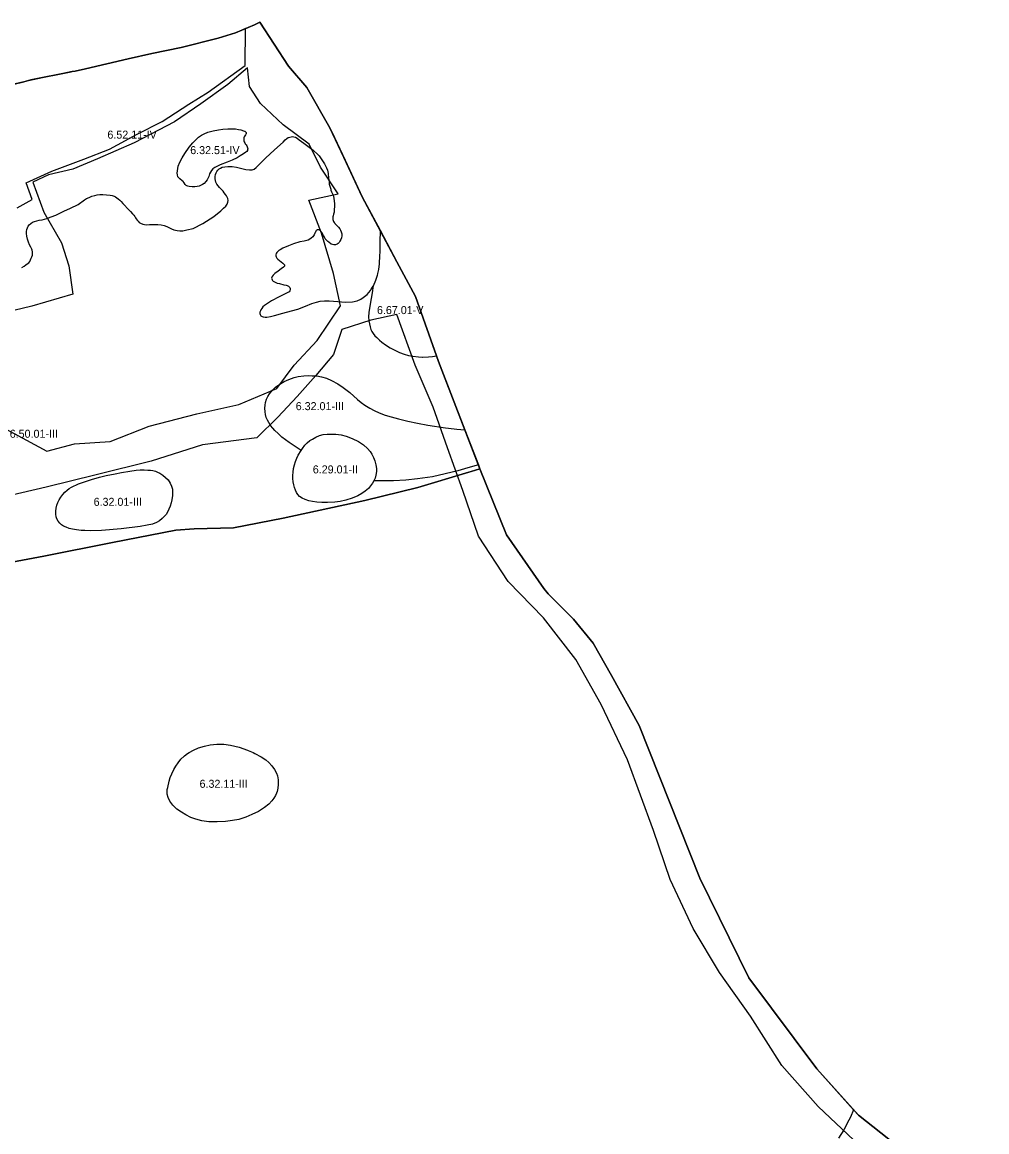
# Model space of a CAD drawing. Extents: x -555156 to -540209, y -1046851 to -1035695.
# Drawn here: x -541747 to -540542, y -1038196 to -1036810 of the extents above; entities that cross this region are included whole.
import ezdxf

# ---------------------------------------------------------------- set-up
doc = ezdxf.new("R2010")
doc.units = 0
for name, color, linetype in [('Vrstva 27', 7, 'Continuous'), ('Vrstva 28', 7, 'Continuous'), ('Vrstva 29', 7, 'Continuous')]:
    doc.layers.add(name, color=color, linetype=linetype)

msp = doc.modelspace()

# ---------------------------------------------------------------- linework, layer by layer
at = {"layer": 'Vrstva 28'}
for points in [[(-541903.43, -1036929.77), (-541877.68, -1036923.71), (-541848.08, -1036913.72), (-541790.28, -1036895.14), (-541767.6, -1036889.55), (-541745.19, -1036884.02), (-541736.43, -1036881.86), (-541685.69, -1036871.7), (-541684.42, -1036871.45), (-541680.65, -1036870.7), (-541667.8, -1036868.13), (-541614.57, -1036855.58), (-541584.97, -1036848.6), (-541548.46, -1036841.46), (-541501.97, -1036829.63), (-541480.4, -1036822.91), (-541472.49, -1036819.6), (-541456.86, -1036813.05), (-541450.16, -1036809.67), (-541414.05, -1036864.8), (-541391.34, -1036891.2), (-541362.63, -1036941.56)], [(-540646.21, -1038219.67), (-540701.89, -1038175.62), (-540754.02, -1038117.46), (-540838.81, -1038003.99), (-540900.32, -1037879.43), (-540976, -1037688.59), (-541010.46, -1037625.98), (-541033.4, -1037585.85), (-541058.08, -1037555.54), (-541089.68, -1037524), (-541094.93, -1037517.52), (-541141.64, -1037450.42), (-541174.98, -1037367.89), (-541226.69, -1037233.48), (-541255.41, -1037152.42), (-541278.92, -1037108.98), (-541321.98, -1037027.74), (-541345.15, -1036978.62), (-541362.63, -1036941.56), (-541391.34, -1036891.2), (-541414.05, -1036864.8), (-541450.16, -1036809.67), (-541456.86, -1036813.05), (-541472.69, -1036819.74), (-541480.4, -1036822.91), (-541501.97, -1036829.63), (-541548.46, -1036841.46), (-541584.97, -1036848.6), (-541667.8, -1036868.13), (-541680.65, -1036870.7), (-541684.42, -1036871.45), (-541745.19, -1036884.02), (-541767.6, -1036889.55)], [(-541538.19, -1036965.9), (-541533.93, -1036960.53), (-541530.23, -1036956.65), (-541526.67, -1036953.41), (-541523.11, -1036950.82), (-541519.78, -1036949.1), (-541514.85, -1036947.12), (-541508.37, -1036945.36), (-541501.67, -1036944.11), (-541496.3, -1036943.28), (-541490.2, -1036942.91), (-541484.74, -1036942.91), (-541480.67, -1036943.1), (-541476.92, -1036943.56), (-541473.73, -1036944.21), (-541470.4, -1036945.36), (-541469.42, -1036945.76), (-541469.01, -1036945.9), (-541468.55, -1036946.13), (-541468.22, -1036946.37), (-541467.98, -1036946.59), (-541467.75, -1036946.89), (-541467.5, -1036947.27), (-541467.33, -1036947.7), (-541467.24, -1036948.17), (-541467.24, -1036948.68), (-541467.33, -1036949.11), (-541467.45, -1036949.44), (-541468.05, -1036950.39), (-541468.89, -1036951.6), (-541469.55, -1036952.82), (-541469.9, -1036954.06), (-541470, -1036955.44), (-541470.05, -1036956.89), (-541469.86, -1036958.13), (-541469.47, -1036959.32), (-541468.94, -1036960.46), (-541468.25, -1036961.63), (-541467.2, -1036962.87), (-541466.24, -1036964.03), (-541465.71, -1036965.3), (-541465.37, -1036966.68), (-541465.24, -1036967.87), (-541465.34, -1036969.03), (-541465.63, -1036970.09), (-541466.27, -1036971.12), (-541467.43, -1036972.23), (-541470.54, -1036974.2), (-541474.43, -1036976.75), (-541478.55, -1036979.2), (-541484.84, -1036982.16), (-541490.84, -1036984.75), (-541499.72, -1036988.03), (-541503.75, -1036990.16), (-541506.43, -1036991.41), (-541508.88, -1036993.03), (-541510.32, -1036994.79), (-541511.75, -1036996.97), (-541512.77, -1036999.37), (-541513.83, -1037002.33), (-541515.82, -1037006.82), (-541517.66, -1037008.91), (-541519.65, -1037011.04), (-541521.83, -1037012.57), (-541525.93, -1037014.41), (-541528.24, -1037015.06), (-541531.31, -1037015.44)], [(-541362.63, -1036941.56), (-541356.79, -1036953.93), (-541343.48, -1036982.15), (-541321.98, -1037027.74), (-541299.74, -1037069.7)], [(-541493.78, -1036990.23), (-541489.97, -1036989.91), (-541484.82, -1036990.04), (-541479.25, -1036991), (-541472.4, -1036992.43), (-541467.39, -1036993.71), (-541462.94, -1036994.1), (-541459.51, -1036994.02), (-541457.29, -1036993.15), (-541454.82, -1036991.34), (-541442.99, -1036979.64), (-541431.57, -1036969.05), (-541420.76, -1036959.44), (-541418.31, -1036956.67), (-541416.13, -1036954.85), (-541414.58, -1036953.94), (-541412.76, -1036953.21), (-541411.03, -1036952.76), (-541409.35, -1036952.62), (-541407.49, -1036952.85), (-541405.62, -1036953.44), (-541403.58, -1036954.67), (-541400.74, -1036956.54), (-541394.93, -1036961), (-541389.99, -1036964.74), (-541383.39, -1036969.44), (-541377.18, -1036975.25), (-541376.11, -1036976.63), (-541373.21, -1036980.35), (-541369.31, -1036986.79), (-541366.68, -1036991.57)], [(-541531.31, -1037015.44), (-541534.48, -1037015.49), (-541538.31, -1037015.09), (-541540, -1037014.7), (-541541.11, -1037014.22), (-541542.18, -1037013.61), (-541543.38, -1037012.36), (-541544.68, -1037010.37), (-541546.02, -1037008.71), (-541547.07, -1037007.75), (-541550.15, -1037005.56), (-541552.33, -1037002.73), (-541553.06, -1037000.3), (-541553.3, -1036998.36), (-541553.06, -1036995.52), (-541552.09, -1036989.56), (-541549.96, -1036984.7), (-541547.05, -1036979.34), (-541543.69, -1036973.59), (-541538.19, -1036965.9)], [(-541734.88, -1037093.42), (-541736.09, -1037090.84), (-541737.76, -1037087.81), (-541739.11, -1037084.71), (-541740.46, -1037080.97), (-541741.34, -1037077.14), (-541741.74, -1037073.8), (-541741.74, -1037071.17), (-541741.34, -1037068.63), (-541740.62, -1037066.48), (-541739.59, -1037064.49), (-541738.24, -1037062.82), (-541736.17, -1037061.06), (-541734.02, -1037059.71), (-541731.55, -1037058.6), (-541728.85, -1037057.8), (-541725.9, -1037057.24), (-541722.24, -1037056.61), (-541716.28, -1037054.78), (-541710.95, -1037053.02), (-541704.94, -1037050.64), (-541695.07, -1037045.94), (-541686.64, -1037042.12), (-541677.17, -1037037.5), (-541669.24, -1037031.86), (-541666.61, -1037030.13), (-541663.42, -1037028.54), (-541659.88, -1037027.17), (-541656.15, -1037026.08), (-541653.28, -1037025.4), (-541650.01, -1037024.99), (-541646.46, -1037024.9), (-541641.6, -1037025.26), (-541637.24, -1037025.67), (-541634.42, -1037026.17), (-541632.05, -1037026.94), (-541630.28, -1037027.85), (-541628.73, -1037028.99), (-541627.14, -1037030.49), (-541625.19, -1037032.13), (-541623.37, -1037033.77), (-541621.14, -1037036.27), (-541619.29, -1037038.22), (-541615.47, -1037042.63), (-541611.6, -1037046.41), (-541609.29, -1037049), (-541607.56, -1037050.82), (-541606.38, -1037052.37), (-541605.38, -1037053.96), (-541604.48, -1037055.42), (-541603.34, -1037057.05), (-541602.25, -1037058.42), (-541600.75, -1037059.92), (-541599.02, -1037060.88), (-541596.43, -1037061.97), (-541594.16, -1037062.47), (-541591.76, -1037062.69), (-541587.94, -1037062.53), (-541582.29, -1037062.45), (-541577.36, -1037062.45), (-541573.3, -1037063.01), (-541569.8, -1037063.73), (-541566.22, -1037065.08), (-541562.95, -1037066.51), (-541560.57, -1037067.71), (-541557.46, -1037069.06), (-541553.57, -1037070.1), (-541549.83, -1037070.34), (-541546.48, -1037070.26), (-541541.15, -1037069.22), (-541533.49, -1037067.27), (-541521.24, -1037061.28), (-541507.63, -1037052.52), (-541498.72, -1037045.51), (-541495.3, -1037042.17), (-541492.39, -1037039.39), (-541490.7, -1037036.93), (-541490.02, -1037034.75), (-541489.84, -1037032.43), (-541490.11, -1037030.15), (-541490.7, -1037028.15), (-541491.61, -1037026.74), (-541492.93, -1037025.01), (-541494.44, -1037022.94), (-541495.98, -1037020.88), (-541500.27, -1037016.35), (-541503.62, -1037011.89), (-541505.01, -1037009.51), (-541505.61, -1037007.51), (-541505.92, -1037005.51), (-541505.74, -1037002.42), (-541505.38, -1037000.19), (-541504.65, -1036997.91), (-541503.6, -1036996.14), (-541502.42, -1036994.68), (-541500.74, -1036993.09), (-541499.24, -1036992.05), (-541497.06, -1036991), (-541493.78, -1036990.23)], [(-541366.68, -1036991.57), (-541365.57, -1036994.67), (-541364.71, -1036998.72), (-541364.08, -1037004.77), (-541363.6, -1037009.15), (-541363.2, -1037012.25), (-541361.53, -1037018.22), (-541361.12, -1037019.68), (-541360.58, -1037021.57), (-541358.59, -1037026.02), (-541357.55, -1037029.45), (-541356.64, -1037036.69), (-541357.35, -1037047.19), (-541357.87, -1037049.6), (-541358.44, -1037051.45), (-541358.73, -1037052.7), (-541358.88, -1037053.87), (-541358.88, -1037054.93), (-541358.68, -1037056.34), (-541358.34, -1037057.64), (-541357.9, -1037058.75), (-541357.2, -1037059.85), (-541356.47, -1037060.78), (-541356.2, -1037061.13), (-541354.37, -1037063.28), (-541354.01, -1037063.64), (-541351.92, -1037065.71), (-541350.05, -1037067.84), (-541349.1, -1037069.62), (-541348.28, -1037071.76), (-541347.73, -1037074.08), (-541347.73, -1037076.76), (-541348.06, -1037079.2), (-541348.64, -1037081.31), (-541349.87, -1037083.4), (-541350.92, -1037084.99), (-541352.1, -1037086.09), (-541353.46, -1037086.9), (-541355.55, -1037087.68), (-541357.65, -1037087.77), (-541359.24, -1037087.59), (-541360.92, -1037086.95), (-541363.87, -1037084.58), (-541364.96, -1037083.67), (-541366.69, -1037082.22), (-541368.42, -1037080.45), (-541369.42, -1037078.49), (-541370.51, -1037076.21), (-541372.69, -1037072.5), (-541373.73, -1037070.94), (-541374.54, -1037070.05), (-541375.52, -1037069.46), (-541376.46, -1037069.17), (-541377.34, -1037069.04), (-541378.2, -1037069.14), (-541378.88, -1037069.35), (-541378.99, -1037069.45), (-541379.5, -1037069.92), (-541380, -1037070.81), (-541380.53, -1037072.18), (-541380.73, -1037072.68), (-541382.14, -1037075.5), (-541383.95, -1037078.05), (-541385.73, -1037079.73), (-541387.5, -1037080.91), (-541389.73, -1037081.87), (-541394.82, -1037083.14), (-541400.05, -1037084.32), (-541407.96, -1037086.55), (-541414.12, -1037089.01), (-541421.44, -1037092.06), (-541424.81, -1037093.97), (-541426.31, -1037094.97), (-541427.67, -1037096.15), (-541428.85, -1037097.52), (-541429.53, -1037098.61), (-541430.08, -1037100.34), (-541430.17, -1037101.61), (-541429.72, -1037102.89), (-541428.67, -1037104.48), (-541427.4, -1037105.59), (-541421.48, -1037110.83), (-541420.44, -1037111.55), (-541419.76, -1037112.26), (-541419.27, -1037113.01), (-541419.08, -1037113.69), (-541419.16, -1037114.41), (-541419.58, -1037115.12), (-541420.38, -1037115.82), (-541423.24, -1037117.92), (-541427.28, -1037120.65), (-541431.24, -1037123.65), (-541433.46, -1037125.6), (-541434.8, -1037127.35), (-541435.25, -1037128.26), (-541435.39, -1037129.35), (-541435.25, -1037130.53), (-541434.8, -1037131.58), (-541434.25, -1037132.31)], [(-541299.74, -1037069.7), (-541299.89, -1037084.87), (-541300.05, -1037089.93), (-541300.21, -1037094.99), (-541300.48, -1037103.36), (-541300.79, -1037109.52), (-541300.9, -1037111.58), (-541301.87, -1037118.55), (-541302.87, -1037123.64), (-541303.4, -1037126.35), (-541304.21, -1037128.63), (-541305.63, -1037132.62), (-541308.42, -1037139.72)], [(-541299.74, -1037069.7), (-541278.92, -1037108.98), (-541255.41, -1037152.42), (-541229.08, -1037226.74)], [(-541747.45, -1037116.34), (-541744.58, -1037114.56), (-541742.36, -1037112.97), (-541740.63, -1037111.65), (-541738.95, -1037110.19), (-541737.67, -1037108.51), (-541736.65, -1037106.66), (-541735.69, -1037104.7), (-541734.92, -1037102.84), (-541734.33, -1037100.83), (-541734.1, -1037098.83), (-541734.24, -1037096.51), (-541734.51, -1037094.74), (-541734.88, -1037093.42)], [(-541434.25, -1037132.31), (-541433.21, -1037133.13), (-541431.66, -1037134.22), (-541430.07, -1037134.99), (-541428.25, -1037135.58), (-541425.48, -1037136.31), (-541420.15, -1037137.83), (-541417.2, -1037138.42), (-541415.74, -1037138.79), (-541414.42, -1037139.47), (-541413.29, -1037140.34), (-541412.56, -1037141.34), (-541412.2, -1037142.56), (-541412.33, -1037143.84), (-541412.56, -1037145.29), (-541413.56, -1037146.48), (-541416.02, -1037147.89), (-541425.83, -1037153.02), (-541435.38, -1037157.89), (-541441.83, -1037162.12), (-541444.06, -1037163.75), (-541446.24, -1037165.44), (-541447.7, -1037167.39), (-541448.83, -1037169.12), (-541449.42, -1037170.53), (-541449.88, -1037172.21), (-541449.92, -1037173.85), (-541449.61, -1037175.08), (-541448.61, -1037176.49), (-541447.29, -1037177.36), (-541445.88, -1037177.86), (-541443.6, -1037178.22), (-541441.47, -1037178.27), (-541436.85, -1037177.59), (-541431.68, -1037176.24), (-541421.34, -1037173.14), (-541416.88, -1037171.9), (-541402.68, -1037168.42), (-541392.93, -1037164.38), (-541385, -1037161.04), (-541379.29, -1037159.36), (-541374.69, -1037158.11), (-541369.26, -1037157.69), (-541363.55, -1037157.83), (-541352.41, -1037158.81), (-541343.36, -1037159.5), (-541334.45, -1037159.09), (-541328.61, -1037157.97), (-541323.87, -1037155.88), (-541320.81, -1037153.79), (-541316.07, -1037150.03), (-541311.76, -1037145.02), (-541311.2, -1037144.13), (-541308.42, -1037139.72)], [(-541308.42, -1037139.72), (-541308.64, -1037141), (-541309.37, -1037145.3), (-541312.6, -1037164.32), (-541313.89, -1037172.5), (-541314.14, -1037177.93), (-541313.73, -1037183.03), (-541313.08, -1037186.76), (-541312.36, -1037190.56), (-541311.47, -1037193.48), (-541310.25, -1037195.99), (-541308.55, -1037198.58), (-541306.37, -1037201.44), (-541303.94, -1037203.87), (-541300.71, -1037206.95), (-541297.63, -1037209.54), (-541293.18, -1037212.78), (-541287.27, -1037216.42), (-541281.28, -1037219.66), (-541275.37, -1037222.34), (-541269.87, -1037224.36), (-541264.44, -1037225.98), (-541258.86, -1037227.11), (-541251.65, -1037227.92), (-541246.97, -1037228.13), (-541246.15, -1037228.17), (-541239.27, -1037227.92)], [(-541239.27, -1037227.92), (-541234.09, -1037227.52), (-541229.08, -1037226.74)], [(-541229.08, -1037226.74), (-541226.69, -1037233.48), (-541193.69, -1037319.27)], [(-541398.21, -1037345.09), (-541413.3, -1037335.01), (-541422.49, -1037328.19), (-541427.29, -1037323.71), (-541431.42, -1037320.04), (-541433.89, -1037317.1), (-541436.67, -1037313.52), (-541438.98, -1037310.01), (-541440.57, -1037307.07), (-541442.08, -1037303.64), (-541442.96, -1037299.74), (-541443.52, -1037296.56), (-541443.84, -1037291.86), (-541443.52, -1037288.04), (-541442.8, -1037284.86), (-541441.53, -1037280.88), (-541439.94, -1037277.37), (-541437.87, -1037274.03), (-541434.05, -1037269.61), (-541430.39, -1037265.87), (-541425.22, -1037262.05), (-541419.81, -1037258.79), (-541413.92, -1037256.08), (-541407.24, -1037253.53), (-541402.14, -1037252.42), (-541394.98, -1037251.54), (-541389.65, -1037251.22), (-541384.64, -1037251.38), (-541378.83, -1037251.7), (-541372.86, -1037252.66), (-541366.82, -1037254.65), (-541360.69, -1037257.43), (-541352.73, -1037261.57), (-541345.73, -1037266.35), (-541337.78, -1037272.4), (-541328.07, -1037281.08), (-541323.33, -1037284.92), (-541318.72, -1037288.1), (-541312.67, -1037291.84), (-541307.1, -1037294.95), (-541300.82, -1037297.89), (-541293.26, -1037300.68), (-541285.86, -1037302.99), (-541276.79, -1037305.3), (-541265.01, -1037308.24), (-541253.16, -1037310.71), (-541240.27, -1037313.26), (-541218.04, -1037316.62), (-541207.22, -1037317.89), (-541203.84, -1037318.29), (-541193.69, -1037319.27)], [(-541193.69, -1037319.27), (-541176.88, -1037362.97)], [(-541398.21, -1037345.09), (-541396.6, -1037342.37), (-541393.82, -1037338.31), (-541390.72, -1037335.29), (-541387.53, -1037332.58), (-541384.43, -1037330.59), (-541379.98, -1037328.2), (-541375.6, -1037326.29), (-541370.75, -1037325.02), (-541365.81, -1037324.46), (-541360.24, -1037324.38), (-541354.99, -1037324.54), (-541348.47, -1037325.34), (-541342.18, -1037326.85), (-541334.86, -1037329.87), (-541326.91, -1037333.61), (-541320.7, -1037337.91), (-541315.53, -1037342.21), (-541312.27, -1037346.03), (-541309.88, -1037349.46), (-541307.97, -1037353.52), (-541306.22, -1037357.66), (-541304.95, -1037362.99), (-541304.31, -1037367.29), (-541304.23, -1037371.11), (-541304.96, -1037375.78), (-541306.01, -1037379.46), (-541307.42, -1037382.87)], [(-541307.42, -1037382.87), (-541309.19, -1037385.69), (-541311.6, -1037389.06), (-541314.42, -1037392.2), (-541318.33, -1037395.56), (-541322.54, -1037398.58), (-541327.71, -1037401.53), (-541334.56, -1037404.47), (-541342.51, -1037407.1), (-541349.51, -1037408.69), (-541356.52, -1037409.57), (-541365.43, -1037409.97), (-541372.75, -1037409.73), (-541378.87, -1037409.25), (-541384.13, -1037408.45), (-541388.98, -1037407.58), (-541393.59, -1037406.15), (-541397.01, -1037404.63), (-541400.28, -1037402.25), (-541402.43, -1037399.86), (-541404.18, -1037397.23), (-541405.45, -1037394.52), (-541406.8, -1037390.94), (-541407.6, -1037387.68), (-541408.31, -1037383.94), (-541408.71, -1037379.72), (-541408.79, -1037376.21), (-541408.47, -1037371.76), (-541407.92, -1037367.54), (-541406.8, -1037362.68), (-541405.69, -1037358.78), (-541403.94, -1037354.48), (-541402.03, -1037350.9), (-541398.21, -1037345.09)], [(-541176.88, -1037362.97), (-541174.98, -1037367.89), (-541185.99, -1037371.19), (-541188.67, -1037371.99), (-541252.66, -1037391.15), (-541318.79, -1037407.17), (-541421.1, -1037429.5), (-541483.07, -1037441.56), (-541532.09, -1037442.9), (-541555.04, -1037444.43), (-541634.35, -1037459.8), (-541720.19, -1037477.06), (-541844.94, -1037500.38)], [(-541176.88, -1037362.97), (-541190.2, -1037366.75), (-541202.45, -1037370.22), (-541234.19, -1037377.6), (-541252.85, -1037380.25), (-541267.47, -1037381.78), (-541283.2, -1037382.75), (-541307.42, -1037382.87)], [(-541844.94, -1037500.38), (-541720.19, -1037477.06), (-541634.35, -1037459.8), (-541555.04, -1037444.43), (-541532.09, -1037442.9), (-541483.07, -1037441.56), (-541421.1, -1037429.5), (-541318.79, -1037407.17), (-541252.66, -1037391.15), (-541188.67, -1037371.99), (-541185.99, -1037371.19), (-541174.98, -1037367.89), (-541141.64, -1037450.42), (-541094.93, -1037517.52), (-541089.68, -1037524), (-541058.08, -1037555.54), (-541033.4, -1037585.85), (-541010.46, -1037625.98), (-540976, -1037688.59)], [(-541668.64, -1037445), (-541673.41, -1037444.68), (-541679.3, -1037443.97), (-541684.16, -1037443.17), (-541688.25, -1037442.19), (-541692.23, -1037440.84), (-541695.25, -1037439.49), (-541697.96, -1037437.74), (-541699.95, -1037435.83), (-541702.1, -1037433.12), (-541703.61, -1037430.41), (-541704.56, -1037427.71), (-541704.96, -1037424.44), (-541704.88, -1037420.62), (-541704.48, -1037417.12), (-541703.61, -1037413.22), (-541702.5, -1037409.79), (-541700.9, -1037406.37), (-541698.91, -1037403.19), (-541696.29, -1037399.84), (-541693.58, -1037396.98), (-541690.72, -1037394.51), (-541688.25, -1037392.44), (-541685.35, -1037390.69), (-541676.68, -1037386.71), (-541669.28, -1037384.01), (-541660.29, -1037380.98), (-541650.35, -1037378.2), (-541641.99, -1037376.21), (-541630.69, -1037373.98), (-541622.74, -1037372.38), (-541612.55, -1037370.55), (-541604.6, -1037369.6), (-541599.66, -1037369.12), (-541594.55, -1037369.02), (-541590.1, -1037369.29), (-541586.6, -1037369.61), (-541583.69, -1037370.06), (-541580.59, -1037370.79), (-541577.91, -1037371.79), (-541575.23, -1037373.16), (-541571.32, -1037375.61), (-541567.95, -1037378.43), (-541564.77, -1037381.62), (-541561.95, -1037385.66), (-541560.5, -1037389.53), (-541559.41, -1037393.26), (-541559.18, -1037396.47), (-541559.27, -1037401.11), (-541560, -1037406.35), (-541560.86, -1037410.26), (-541562.09, -1037414.35), (-541563.63, -1037418.08), (-541565.5, -1037421.86), (-541567.21, -1037424.73), (-541569.12, -1037427.09), (-541571.94, -1037429.96), (-541575.48, -1037432.78), (-541579.35, -1037434.92), (-541584.21, -1037436.74), (-541590.85, -1037438.28), (-541599.81, -1037439.7), (-541623.37, -1037442.75), (-541647.87, -1037444.82)], [(-541647.87, -1037444.82), (-541661.8, -1037445.08), (-541668.64, -1037445)], [(-540976, -1037688.59), (-540900.32, -1037879.43), (-540838.81, -1038003.99), (-540754.02, -1038117.46), (-540707.94, -1038168.87)], [(-541492.96, -1037808.43), (-541503.37, -1037809.02), (-541513.61, -1037808.77), (-541522.66, -1037807.57), (-541530.08, -1037805.67), (-541536.31, -1037803.37), (-541542.63, -1037800.29), (-541548.09, -1037796.88), (-541553.64, -1037793.12), (-541558.68, -1037788.25), (-541562.43, -1037783.13), (-541564.57, -1037778.34), (-541565.85, -1037774.16), (-541566.02, -1037770.92), (-541565.68, -1037768.61), (-541565.15, -1037766.03), (-541563.36, -1037758.26), (-541562.08, -1037753.48), (-541560.2, -1037749.04), (-541557.64, -1037743.57), (-541555.08, -1037739.3), (-541552.26, -1037735.12), (-541548.76, -1037730.76), (-541544.57, -1037726.74), (-541544.41, -1037726.58), (-541540.27, -1037723.66)], [(-541540.27, -1037723.66), (-541538.35, -1037722.31), (-541533.06, -1037719.32), (-541526.74, -1037716.59), (-541519.06, -1037714.28), (-541512.32, -1037712.74), (-541503.61, -1037711.97), (-541494.99, -1037711.97), (-541486.8, -1037713.08), (-541475.96, -1037715.65), (-541465.37, -1037719.4), (-541464.67, -1037719.71), (-541458.45, -1037722.45), (-541456.24, -1037723.42), (-541448.32, -1037727.8), (-541442.51, -1037731.56), (-541438.67, -1037734.8), (-541435.17, -1037738.9), (-541431.67, -1037743.51), (-541429.11, -1037747.95), (-541428, -1037751.46), (-541427.23, -1037756.41), (-541426.98, -1037762.39), (-541427.41, -1037766.83), (-541428.26, -1037770.93), (-541429.12, -1037773.18), (-541430.54, -1037775.96), (-541432.59, -1037779.38), (-541434.98, -1037782.55), (-541438.88, -1037786.75), (-541444.34, -1037791.14), (-541451.73, -1037795.87), (-541460.09, -1037799.89), (-541467.61, -1037803.22), (-541476.48, -1037805.95), (-541484.25, -1037807.4), (-541492.96, -1037808.43)], [(-540707.94, -1038168.87), (-540712.06, -1038177.82), (-540713.9, -1038181.83), (-540720.31, -1038193.6), (-540726.84, -1038204.06)], [(-540707.94, -1038168.87), (-540701.89, -1038175.62), (-540646.21, -1038219.67), (-540541.51, -1038323.17)]]:
    msp.add_lwpolyline(points, dxfattribs=at)
at = {"layer": 'Vrstva 29'}
for points in [[(-541753.304999, -1037041.599), (-541734.39, -1037031.072003), (-541741.924006, -1037010.488005), (-541709.982002, -1036995.888996), (-541670.035995, -1036980.711999), (-541638.082001, -1036968.160001), (-541603.388994, -1036949.800002), (-541572.277004, -1036933.568998), (-541538.738001, -1036912.002993), (-541514.710005, -1036897.228009), (-541468.506998, -1036863.878003), (-541467.921627, -1036817.68555), (-541472.49, -1036819.6), (-541480.4, -1036822.91), (-541501.97, -1036829.63), (-541548.46, -1036841.46), (-541584.97, -1036848.6), (-541614.570176, -1036855.579252), (-541667.8, -1036868.13), (-541680.65, -1036870.7), (-541684.42, -1036871.45), (-541685.69, -1036871.7), (-541736.43, -1036881.86), (-541745.19, -1036884.02), (-541766.527409, -1036889.285322)], [(-541716.299988, -1037345.896973), (-541681.676025, -1037336.731995), (-541637.02301, -1037333.619995), (-541588.400024, -1037314.364014), (-541528.973022, -1037298.953003), (-541476.39502, -1037287.327026), (-541428.973999, -1037267.416992), (-541407.083008, -1037238.325989), (-541378.330017, -1037207.497009), (-541349.369019, -1037164.164978), (-541357.875, -1037123.779907), (-541373.125, -1037073.385986), (-541388.697998, -1037032.15802), (-541352.176025, -1037024.242004), (-541374.067993, -1036990.951904), (-541388.557007, -1036962.125), (-541420.987976, -1036937.804993), (-541449.333008, -1036911.414978), (-541463.146912, -1036889.827026), (-541465.495911, -1036866.538025), (-541490.020996, -1036887.64502), (-541523.859009, -1036911.731995), (-541556.731018, -1036934.143982), (-541607.231995, -1036960.590027), (-541652.856018, -1036980.460022), (-541683.830994, -1036993.383911), (-541714.338013, -1037000.22699), (-541733.637024, -1037009.685974), (-541719.916016, -1037047.114014), (-541697.835999, -1037085.283997), (-541688.960022, -1037113.953003), (-541683.72998, -1037149.60199), (-541735.184021, -1037164.684998), (-541791.031006, -1037177.96698)], [(-540707.765991, -1038206.549003), (-540752.159002, -1038164.440001), (-540797.804005, -1038113.490001), (-540837.022002, -1038051.546008), (-540875.595003, -1037997.092995), (-540908.494997, -1037942.293999), (-540937.051998, -1037881.109992), (-540957.918009, -1037819.820997), (-540990.423007, -1037731.578004), (-541023.409993, -1037662.451992), (-541055.091, -1037606.007998), (-541095.507999, -1037554.148008), (-541139.763991, -1037508.732007), (-541176.775008, -1037451.909006), (-541196.353992, -1037394.863006), (-541215.624993, -1037341.689006), (-541233.622009, -1037290.712998), (-541256.071002, -1037238.437992), (-541278.716009, -1037174.890996), (-541311.301996, -1037181.999008), (-541347.486995, -1037193.534002), (-541358.111005, -1037224.736005), (-541379.925004, -1037251.023991), (-541403.535, -1037277.352996), (-541427.589998, -1037303.117994), (-541453.977005, -1037329.115992), (-541521.831002, -1037337.897994), (-541585.956998, -1037358.373007), (-541654.800997, -1037375.473), (-541717.034996, -1037390.804992), (-541778.362009, -1037404.966993)], [(-541772.539978, -1037315.158997), (-541716.299988, -1037345.896973)]]:
    msp.add_lwpolyline(points, dxfattribs=at)

# ---------------------------------------------------------------- texts
at = {"layer": 'Vrstva 27'}
for s, p in [('6.52.11-IV', (-541640.557241, -1036955.2)), ('6.32.51-IV', (-541537.067241, -1036974.55)), ('6.67.01-V', (-541303.661006, -1037174.42)), ('6.32.01-III', (-541405.186548, -1037294.46)), ('6.50.01-III', (-541762.626548, -1037328.95)), ('6.29.01-II', (-541383.860313, -1037373.51)), ('6.32.01-III', (-541657.756548, -1037414.02)), ('6.32.11-III', (-541525.386548, -1037766.37))]:
    msp.add_text(s, height=10, dxfattribs=at).set_placement(p)

doc.saveas('drawing.dxf')
